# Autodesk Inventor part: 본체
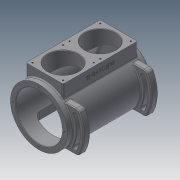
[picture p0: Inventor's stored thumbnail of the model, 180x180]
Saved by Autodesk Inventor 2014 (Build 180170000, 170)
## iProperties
Created: 2016-11
Part Number: 본체
Material: 알루미늄 6061
Document SubType Name: Modeling
Designer: mduedu
Density: 2.71 g/cm^3
Mass: 2488.99 g
Surface Area: 1764.74 cm^2
Volume: 918.447 cm^3
Appearance: 기본값
Author: mduedu
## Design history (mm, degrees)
sketch "스케치1"
  geometry: C1 r 65 at (0, 0); 1 further point
  constraints: 1 centre point, 1 coincident
  dimensions: "d119" = 130 diameter of C1
extrude "돌출1" new body sketch "스케치1" distance "d3" = 98; taper "d4" = 0 deg; dims "d132" = 97, "d133" = 0
feature "쉘1" dims "d120" = 12, "d134" = 8
node "작업 평면2"
sketch "스케치13"
  geometry: L1 (42.5, 85)-(-42.5, 85); L2 (-42.5, 85)-(-42.5, -85); L3 (-42.5, -85)-(42.5, -85); L4 (42.5, -85)-(42.5, 85); 2 further points
  constraints: 8 end point, 2 parallel, 1 horizontal, 1 midpoint, 1 perpendicular, 1 vertical alignment
  dimensions: "d122" = 170 distance of L1.end L2.end; "d124" = 85 distance of L2.end L3.end; "d125" = 85 distance from line of point (0, 0) L1 (= 0.5 x d122)
extrude "돌출11" join sketch "스케치13" stored distance "d126" = 10; taper "d127" = 0 deg
sketch "스케치14"
  geometry: L1 (65, 97)-(-65, 97) reference; C1 r 35 at (0, 42.5); 1 further point
  constraints: 1 centre point, 1 vertical alignment
  dimensions: "d128" = 70 diameter of C1; "d129" = 54.5 distance from line of C1.centre L1
extrude "돌출12" cut sketch "스케치14" stored distance "d130" = 10; taper "d131" = 0 deg
sketch "스케치15"
  geometry: C1 r 53 at (0, 0) reference; 1 further point
extrude "돌출13" cut sketch "스케치15" stored distance "d135" = 10; taper "d136" = 0 deg
chamfer "모따기1" distance "d54" = 1; stored, may be unused: second distance "d55" = 2, angle "d56" = 45 deg
sketch "스케치8"
  geometry: C1 r 23 at (0, 0); C2 r 65 at (0, 0) reference; 1 further point
  constraints: 1 centre point, 1 concentric
  dimensions: "d57" = 46 diameter of C1
extrude "돌출8" join sketch "스케치8" distance "d58" = 14; taper "d59" = 0 deg
hole "구멍3" diameter "d62" = 24; stored, may be unused: countersink angle "d66" = 90 deg, drill point angle "d68" = 0 deg; dims "d63" = 6, "d64" = 28, "d65" = 8, "d67" = 14, "d169" = 10, "d170" = 10
fillet "모깎기11" dims "d69" = 3
fillet "모깎기12" dims "d70" = 3
fillet "모깎기13" dims "d71" = 0.3
chamfer "모따기2" distance "d72" = 1; stored, may be unused: second distance "d73" = 2, angle "d74" = 45 deg
node "작업 평면3"
sketch "스케치16"
  geometry: L1 (-42.5, -80)-(47.5, -80); L2 (-42.5, -80)-(21.14, -16.36); L3 (-42.5, -80)-(21.14, -143.64); L4 (3.462, -34.038)-(34.879, -34.038); L5 (3.462, -125.962)-(34.879, -125.962); A1 r 65 centre (-42.5, -80) between (3.462, -34.038) and (3.462, -125.962) reference; A2 r 90 centre (-42.5, -80) between (34.879, -125.962) and (34.879, -34.038); A3 r 90 centre (-42.5, -80) between (34.879, -34.038) and (34.879, -125.962); A4 r 65 centre (-42.5, -80) between (3.462, -125.962) and (3.462, -34.038); 1 further point
  constraints: 11 point on circle, 10 end point, 3 centre point, 2 parallel, 2 point on line, 1 coincident, 1 horizontal
  dimensions: "d140" = 45 deg angle of L3 L1; "d141" = 45 deg angle of L2 L1; "d142" = 25 radial gap between concentric circles of A1 A2
extrude "돌출14" join sketch "스케치16" distance "d143" = 15; taper "d144" = 0 deg
sketch "스케치17"
  geometry: L1 (-42.5, -80)-(34.414, -80); L2 (-42.5, -80)-(27.208, -47.495); L3 (-42.5, -80)-(27.208, -112.505); L4 (34.879, -34.038)-(3.462, -34.038) reference; L5 (3.462, -125.962)-(34.879, -125.962) reference; A1 r 65 centre (-42.5, -80) between (3.462, -34.038) and (3.462, -125.962) reference; A2 r 76.914 centre (-42.5, -80) between (19.17, -125.962) and (19.17, -34.038); A3 r 4 centre (27.208, -47.495) between (23.582, -49.185) and (30.833, -45.804); A4 r 4 centre (27.208, -112.505) between (30.833, -114.196) and (23.582, -110.815); A5 r 80.914 centre (-42.5, -80) between (30.833, -114.196) and (30.833, -45.804); A6 r 72.914 centre (-42.5, -80) between (23.582, -110.815) and (23.582, -49.185); 1 further point
  constraints: 13 point on circle, 6 end point, 5 centre point, 5 coincident, 3 midpoint, 2 point on line, 1 equal radius, 1 horizontal
  dimensions: "d145" = 25 deg angle of L1 L3; "d146" = 25 deg angle of L2 L1; "d147" = 8 diameter of A3
extrude "돌출15" cut sketch "스케치17" stored distance "d150" = 15; taper "d151" = 0 deg
fillet "모깎기17" dims "d152" = 10
fillet "모깎기18" dims "d153" = 2
fillet "모깎기19" dims "d154" = 2
chamfer "모따기4" distance "d155" = 1; stored, may be unused: second distance "d156" = 2, angle "d157" = 45 deg
fillet "모깎기20" dims "d159" = 3
fillet "모깎기21" dims "d160" = 3
fillet "모깎기22" dims "d161" = 3
node "작업 평면4"
sketch "스케치18"
  geometry: L1 (-42.5, 65)-(42.5, 65); L2 (42.5, 65)-(42.5, -65); L3 (42.5, -65)-(-42.5, -65); L4 (-42.5, -65)-(-42.5, 65); 2 further points
  constraints: 8 end point, 2 parallel, 1 horizontal, 1 midpoint, 1 perpendicular, 1 vertical alignment
  dimensions: "d162" = 130 distance of L1.end L2.end; "d164" = 85 distance of L2.end L3.end; "d165" = 65 distance from line of point (0, 0) L1 (= 0.5 x d162)
extrude "돌출16" cut sketch "스케치18" stored distance "d166" = 15; taper "d167" = 0 deg
fillet "모깎기23" dims "d168" = 10
fillet "모깎기24" dims "d173" = 3
sketch "스케치19"
  geometry: 4 further points
  constraints: 4 other
hole "구멍6" sketch "스케치19" at (0, -59), (59, 0), (-59, 0), (0, 59) diameter "d174" = 3.242; stored, may be unused: countersink angle "d178" = 90 deg, drill point angle "d180" = 120 deg; dims "d175" = 7, "d176" = 4, "d177" = 2, "d179" = 9
sketch "스케치20"
  geometry: L1 (35, -77.5)-(-35, -77.5); L2 (-35, -77.5)-(-35, -7.5); L3 (-35, -7.5)-(35, -7.5); L4 (35, -7.5)-(35, -77.5); L5 (35, -77.5)-(-35, -7.5); L6 (-35, -77.5)-(35, -7.5); C1 r 36 at (0, -42.5) reference; 5 further points
  constraints: 12 end point, 4 coincident, 2 midpoint, 2 parallel, 1 horizontal, 1 perpendicular
  dimensions: "d181" = 70 distance of L2.end L3.end; "d182" = 70 distance of L1.end L2.end
hole "구멍7" sketch "스케치20" at (-35, -77.5), (-35, -7.5), (35, -7.5), (35, -77.5) diameter "d183" = 3.242; stored, may be unused: countersink angle "d187" = 90 deg, drill point angle "d189" = 118 deg; dims "d184" = 7, "d185" = 4, "d186" = 2, "d188" = 9
sketch "스케치21"
  geometry: L1 (164, 0)-(0, 0) reference; L2 (-3, 0)-(-3, -24.649) reference; 3 further points
  constraints: 1 midpoint, 1 vertical alignment, 1 other
  dimensions: "d190" = 15 distance from line of point (82, -15) L1; "d191" = 85 distance from line of point (82, 0) L2 (derived)
feature "엠보싱2" sketch "스케치21" dims "d3" = 98, "d4" = 0, "d119" = 130, "d132" = 97, "d133" = 0, "d192" = 0.5, "d193" = 0
node "솔리드1"
mirror "대칭5"
mirror "대칭6"
mirror "대칭7"
